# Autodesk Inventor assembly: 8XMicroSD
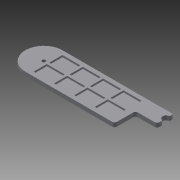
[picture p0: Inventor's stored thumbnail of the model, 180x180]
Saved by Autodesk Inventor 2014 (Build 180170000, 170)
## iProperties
Created: 2015-01
Part Number: 8XMicroSD
Document SubType Name: Assembly
Designer: Drano
Author: Drano
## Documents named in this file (3)
- C:\Users\Drano\Documents\SD swiss army\8XMicroSD.iam
- C:\Users\Drano\Documents\SD swiss army\backplate.ipt
- C:\Users\Drano\Documents\SD swiss army\8XMicroSD.ipt
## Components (2 placed, 2 different names)
1. backplate:1 — Mate:1, Mate:2, Flush:1
2. 8XMicroSD:1 — Mate:1, Mate:2, Flush:1
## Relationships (3: Mate 2, Flush 1)
- Mate:1: backplate:1 ↔ 8XMicroSD:1
- Mate:2: backplate:1 ↔ 8XMicroSD:1
- Flush:1: backplate:1 ↔ 8XMicroSD:1
